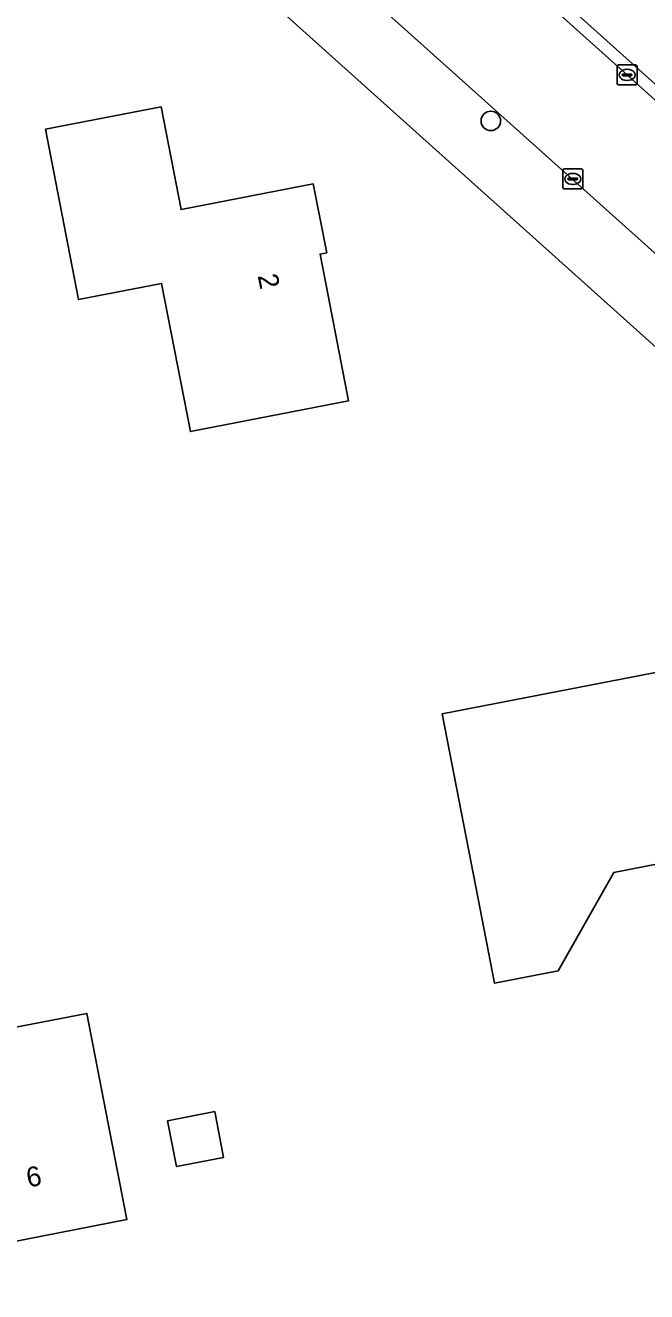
# Model space of a CAD drawing. Extents: x 157648 to 158502, y 379212 to 380938.
# Drawn here: x 158308.7 to 158339.9, y 380251.4 to 380315 of the extents above; entities that cross this region are included whole.
import ezdxf

# ---------------------------------------------------------------- set-up
doc = ezdxf.new("R2010")
doc.units = 0
for name, color, linetype in [('IMGEO_Boom', 7, 'Continuous'), ('IMGEO_Erf', 7, 'Continuous'), ('IMGEO_Kolk', 7, 'Continuous'), ('IMGEO_Pand', 7, 'Continuous'), ('IMGEO_Pand_nummerreeks', 7, 'Continuous'), ('IMGEO_Rijbaan_lokaal_open', 7, 'Continuous'), ('IMGEO_Voetpad_open', 7, 'Continuous')]:
    doc.layers.add(name, color=color, linetype=linetype)

msp = doc.modelspace()

# ---------------------------------------------------------------- linework, layer by layer
at = {"layer": 'IMGEO_Boom'}
msp.add_circle((158332.065, 380310.16), 0.489, dxfattribs=at)
at = {"layer": 'IMGEO_Erf'}
for points in [[(158355.536, 380284.979), (158355.63, 380285.086), (158319.878, 380317.192), (158319.785, 380317.098), (158313.914, 380322.39), (158312.921, 380322.194), (158264.365, 380312.705), (158256.222, 380311.09), (158254.843, 380310.82), (158258.955, 380273.913), (158254.984, 380250), (158254.861, 380249.262), (158262.709, 380236.893), (158282.59, 380240.787), (158328.358, 380249.669)], [(158328.87, 380322.271), (158368.445, 380286.775), (158375.993, 380286.676), (158378.309, 380289.272), (158394.201, 380307.087)]]:
    msp.add_lwpolyline(points, dxfattribs=at)
for points in [[(158311.388, 380301.195), (158309.725, 380309.738), (158315.527, 380310.867), (158316.532, 380305.706), (158318.251, 380306.041), (158323.159, 380306.996), (158323.831, 380303.545), (158323.499, 380303.48), (158324.933, 380296.113), (158316.998, 380294.568), (158315.551, 380302.005)], [(158329.622, 380280.401), (158343.351, 380283.073), (158344.504, 380277.15), (158349.423, 380278.107), (158350.945, 380270.286), (158344.65, 380269.061), (158343.781, 380273.526), (158338.235, 380272.446), (158335.451, 380267.512), (158332.252, 380266.889), (158331.428, 380271.121)], [(158312.856, 380259.93), (158313.811, 380255.022), (158305.427, 380253.39), (158304.888, 380256.162), (158304.62, 380257.539), (158298.23, 380256.295), (158298.498, 380254.918), (158294.555, 380254.15), (158293.6, 380259.058), (158293.23, 380260.956), (158303.541, 380262.963), (158303.39, 380263.739), (158302.817, 380266.684), (158303.608, 380267.856), (158306.052, 380268.332), (158307.224, 380267.542), (158307.797, 380264.597), (158311.796, 380265.375)], [(158318.216, 380260.442), (158318.662, 380258.148), (158316.299, 380257.688), (158315.852, 380259.982)]]:
    msp.add_lwpolyline(points, close=True, dxfattribs=at)
at = {"layer": 'IMGEO_Kolk'}
for p, q in [((158338.4, 380312.042), (158338.4, 380312.894)), ((158338.475, 380312.968), (158339.327, 380312.968)), ((158338.888, 380312.748), (158338.913, 380312.748)), ((158339.401, 380312.894), (158339.401, 380312.042)), ((158339.327, 380311.968), (158338.475, 380311.968)), ((158338.659, 380312.462), (158338.659, 380312.474)), ((158339.097, 380312.425), (158338.699, 380312.425)), ((158338.702, 380312.511), (158339.1, 380312.511)), ((158338.911, 380312.188), (158338.886, 380312.188)), ((158339.143, 380312.474), (158339.143, 380312.462)), ((158335.678, 380306.821), (158335.678, 380307.673)), ((158335.753, 380307.747), (158336.605, 380307.747)), ((158336.166, 380307.527), (158336.191, 380307.527)), ((158336.679, 380307.673), (158336.679, 380306.821)), ((158335.937, 380307.241), (158335.937, 380307.253)), ((158336.375, 380307.204), (158335.977, 380307.204)), ((158335.98, 380307.29), (158336.378, 380307.29)), ((158336.189, 380306.967), (158336.164, 380306.967)), ((158336.421, 380307.253), (158336.421, 380307.241)), ((158336.605, 380306.747), (158335.753, 380306.747))]:
    msp.add_line(p, q, dxfattribs=at)
for points in [[(158338.4, 380312.042), (158338.4, 380312.894)], [(158338.475, 380312.968), (158339.327, 380312.968)], [(158339.401, 380312.894), (158339.401, 380312.042)], [(158339.327, 380311.968), (158338.475, 380311.968)], [(158335.678, 380306.821), (158335.678, 380307.673)], [(158335.753, 380307.747), (158336.605, 380307.747)], [(158336.679, 380307.673), (158336.679, 380306.821)], [(158336.605, 380306.747), (158335.753, 380306.747)]]:
    msp.add_lwpolyline(points, dxfattribs=at)
for centre, radius, start, end in [((158338.477, 380312.892), 0.0765, 91.55205, 178.44795), ((158338.477, 380312.892), 0.0765, 91.55205, 178.44795), ((158339.325, 380312.892), 0.0765, 1.55205, 88.44795), ((158339.325, 380312.892), 0.0765, 1.55205, 88.44795), ((158338.477, 380312.044), 0.0765, 181.55205, 268.44795), ((158338.477, 380312.044), 0.0765, 181.55205, 268.44795), ((158338.699, 380312.471), 0.0403, 85.87752, 175.75265), ((158338.696, 380312.461), 0.0366, 178.93798, 274.71019), ((158339.1, 380312.468), 0.043, 264.86636, 352.45326), ((158339.104, 380312.473), 0.0386, 1.73085, 96.63898), ((158339.325, 380312.044), 0.0765, 271.55205, 358.44795), ((158339.325, 380312.044), 0.0765, 271.55205, 358.44795), ((158335.755, 380307.671), 0.0765, 91.55205, 178.44795), ((158335.755, 380307.671), 0.0765, 91.55205, 178.44795), ((158336.603, 380307.671), 0.0765, 1.55205, 88.44795), ((158336.603, 380307.671), 0.0765, 1.55205, 88.44795), ((158335.977, 380307.25), 0.0403, 85.87752, 175.75265), ((158335.974, 380307.24), 0.0366, 178.93798, 274.71019), ((158336.378, 380307.247), 0.043, 264.86636, 352.45326), ((158336.382, 380307.252), 0.0386, 1.73085, 96.63898), ((158335.755, 380306.823), 0.0765, 181.55205, 268.44795), ((158335.755, 380306.823), 0.0765, 181.55205, 268.44795), ((158336.603, 380306.823), 0.0765, 271.55205, 358.44795), ((158336.603, 380306.823), 0.0765, 271.55205, 358.44795)]:
    msp.add_arc(centre, radius, start, end, dxfattribs=at)
for centre, major_axis, ratio, start_param, end_param in [((158338.887, 380312.468), (-0.387, 0.002), 0.722429, 4.712389, 7.853982), ((158338.912, 380312.468), (-0.39, 0.002), 0.717154, 1.570796, 4.712389), ((158336.165, 380307.247), (-0.387, 0.002), 0.722429, 4.712389, 7.853982), ((158336.19, 380307.247), (-0.39, 0.002), 0.717154, 1.570796, 4.712389)]:
    msp.add_ellipse(centre, major_axis=major_axis, ratio=ratio, start_param=start_param, end_param=end_param, dxfattribs=at)
at = {"layer": 'IMGEO_Pand'}
for points in [[(158315.527, 380310.867), (158309.725, 380309.738), (158311.388, 380301.195), (158315.551, 380302.005), (158316.998, 380294.568), (158324.933, 380296.113), (158323.499, 380303.48), (158323.831, 380303.545), (158323.159, 380306.996), (158318.251, 380306.041), (158316.532, 380305.706)], [(158343.351, 380283.073), (158329.622, 380280.401), (158331.428, 380271.121), (158332.252, 380266.889), (158335.451, 380267.512), (158338.235, 380272.446), (158343.781, 380273.526), (158344.65, 380269.061), (158350.945, 380270.286), (158349.423, 380278.107), (158344.504, 380277.15)], [(158312.856, 380259.93), (158311.796, 380265.375), (158307.797, 380264.597), (158307.224, 380267.542), (158306.052, 380268.332), (158303.608, 380267.856), (158302.817, 380266.684), (158303.39, 380263.739), (158303.541, 380262.963), (158293.23, 380260.956), (158293.6, 380259.058), (158294.555, 380254.15), (158298.498, 380254.918), (158298.23, 380256.295), (158304.62, 380257.539), (158304.888, 380256.162), (158305.427, 380253.39), (158313.811, 380255.022)], [(158316.299, 380257.688), (158318.662, 380258.148), (158318.216, 380260.442), (158315.852, 380259.982)]]:
    msp.add_lwpolyline(points, close=True, dxfattribs=at)
at = {"layer": 'IMGEO_Rijbaan_lokaal_open'}
for points in [[(158369.829, 380284.728), (158368.046, 380286.323), (158351.223, 380301.374), (158347.107, 380305.076), (158338.137, 380313.159), (158333.974, 380316.904), (158322.192, 380327.468)], [(158315.578, 380325.699), (158316.461, 380324.918), (158316.931, 380324.502), (158319.899, 380321.823), (158358.695, 380287.026), (158363.19, 380282.962), (158365.367, 380281.05), (158374.084, 380273.393), (158375.361, 380274.822)]]:
    msp.add_lwpolyline(points, dxfattribs=at)
at = {"layer": 'IMGEO_Voetpad_open'}
for points in [[(158322.192, 380327.468), (158333.974, 380316.904), (158338.137, 380313.159), (158347.107, 380305.076), (158351.223, 380301.374), (158368.046, 380286.323), (158368.445, 380286.775), (158328.87, 380322.271)], [(158319.899, 380321.823), (158316.931, 380324.502), (158316.461, 380324.918), (158313.914, 380322.39), (158319.785, 380317.098), (158319.878, 380317.192), (158355.63, 380285.086), (158355.536, 380284.979), (158362.946, 380278.347)], [(158365.367, 380281.05), (158363.19, 380282.962), (158362.892, 380282.636), (158358.392, 380286.698), (158358.695, 380287.026), (158319.899, 380321.823)]]:
    msp.add_lwpolyline(points, dxfattribs=at)

# ---------------------------------------------------------------- texts
at = {"layer": 'IMGEO_Pand_nummerreeks'}
for s, rotation, p in [('2', 281.01499, (158320.369, 380302.393)), ('6', 11.01524, (158308.867, 380256.628))]:
    msp.add_text(s, height=1, rotation=rotation, dxfattribs=at).set_placement(p)

doc.saveas('drawing.dxf')
